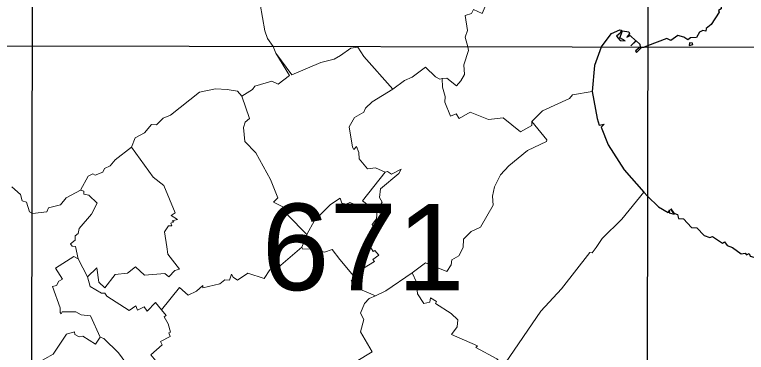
# Model space of a CAD drawing. Extents: x 483840 to 488445, y 4386047 to 4389027.
# Drawn here: x 488113.7 to 488278.3, y 4388075.6 to 4388151.7 of the extents above; entities that cross this region are included whole.
import ezdxf
from ezdxf.enums import TextEntityAlignment as Align

# ---------------------------------------------------------------- set-up
doc = ezdxf.new("R2010")
doc.units = 0
doc.header["$LTSCALE"] = 4
doc.linetypes.add('DOTTED', pattern=[1.5, 0.3, -1.2])
for name, color, linetype, lineweight in [('1', 7, 'Continuous', 13), ('2', 7, 'DOTTED', 13), ('3', 7, 'Continuous', 25)]:
    doc.layers.add(name, color=color, linetype=linetype, lineweight=lineweight)

msp = doc.modelspace()

# ---------------------------------------------------------------- linework, layer by layer
at = {"layer": '1', "lineweight": 25}
for p, q in [((488116.81, 4387693.08), (488117.86, 4388235.03)), ((488255.37, 4387692.81), (488256.42, 4388234.76)), ((487979.13, 4388144.96), (488394.81, 4388144.16))]:
    msp.add_line(p, q, dxfattribs=at)
at = {"layer": '3'}
msp.add_line((488256.11, 4388144.69), (488255.33, 4388144.38), dxfattribs=at)
at = {"layer": '3', "lineweight": 13}
msp.add_line((488171.85, 4388144.53), (488172.45, 4388143.01), dxfattribs=at)
for points in [[(488164.04, 4388180.35), (488162.48, 4388179.07), (488162.63, 4388175.3), (488163.18, 4388174.87), (488163.68, 4388173.06), (488163.73, 4388169.67), (488165.91, 4388166.46), (488167.69, 4388165.71), (488167.55, 4388163.6), (488168.76, 4388162.25), (488168.71, 4388160.94), (488169.4, 4388159.34), (488169.66, 4388157.36), (488169.51, 4388155.19), (488168.92, 4388154.04), (488169.96, 4388148.07), (488170.6, 4388146.32), (488171.85, 4388144.53)], [(488231.17, 4388164.34), (488228.87, 4388163.4), (488224.37, 4388157.78), (488222.57, 4388156.35), (488221.87, 4388155.14), (488220.08, 4388154.77), (488218.9, 4388151.95), (488216.97, 4388152.84), (488216.47, 4388152), (488215.05, 4388151.49), (488215.57, 4388148.17), (488215.09, 4388146.67), (488215.64, 4388144.44)], [(488172.45, 4388143.01), (488175.54, 4388138.02), (488173, 4388136.09), (488171.54, 4388136.73), (488167.69, 4388135.58), (488167.17, 4388134.85), (488164.81, 4388133.38)], [(488172.45, 4388143.01), (488176.05, 4388138.15), (488182.61, 4388140.92), (488185.61, 4388141.66), (488186.99, 4388142.51)], [(488198.76, 4388134.96), (488192.28, 4388142.29), (488190.88, 4388144.37), (488189.35, 4388144.13), (488186.99, 4388142.51)], [(488215.64, 4388144.44), (488215.83, 4388143.61), (488214.77, 4388140.44), (488214.88, 4388138.22), (488214.08, 4388136.84), (488213.11, 4388135.65), (488210.93, 4388137.41), (488209.88, 4388137.32)], [(488209.88, 4388137.32), (488209.37, 4388137.17), (488208.41, 4388137.72), (488206.1, 4388139.92), (488203.15, 4388137.65), (488201.38, 4388136.87), (488198.76, 4388134.96)], [(488230.06, 4388127.66), (488230.09, 4388126.71), (488227.5, 4388125.33), (488223.62, 4388128.44), (488220.32, 4388128.11), (488216.21, 4388129.72), (488213.69, 4388128.29), (488213.04, 4388129.4), (488211.76, 4388128.83), (488210.46, 4388132.03), (488210.59, 4388133.29), (488209.93, 4388135.37), (488209.88, 4388137.32)], [(488164.81, 4388133.38), (488163.84, 4388134.44), (488161.53, 4388134.86), (488158.89, 4388134.97), (488155.24, 4388134.28), (488148.75, 4388129.05), (488147.12, 4388128.42), (488145.58, 4388126.92), (488144.49, 4388126.94), (488142.92, 4388125.08), (488140.82, 4388123.97), (488139.98, 4388121.9)], [(488198.76, 4388134.96), (488194.14, 4388132.11), (488192.61, 4388130.65), (488192.26, 4388129.72), (488190.13, 4388128.52), (488188.92, 4388126.43), (488189.73, 4388121.87), (488189.98, 4388121.32), (488190.57, 4388122.02), (488191.14, 4388120.63), (488191.2, 4388119.2), (488193.09, 4388116.98), (488194.85, 4388117.24), (488197.06, 4388116.24)], [(488164.81, 4388133.38), (488166.56, 4388128.34), (488165.55, 4388127.46), (488165.16, 4388126.29), (488165.46, 4388123.12), (488167.93, 4388120.56), (488171.27, 4388114.58), (488172.92, 4388110.44), (488171.92, 4388109.47), (488174.96, 4388107.94), (488174.44, 4388107.44), (488175.08, 4388106.62), (488179.43, 4388102.16), (488178.31, 4388099.33)], [(488243.61, 4388134.37), (488239.22, 4388133.68), (488238.5, 4388132.84), (488232.47, 4388130.07), (488230.06, 4388127.66)], [(488230.06, 4388127.66), (488233.44, 4388123.49), (488233.35, 4388123.17), (488229.07, 4388121.1), (488224.86, 4388117.69), (488223.01, 4388115.65), (488221.67, 4388112.93), (488221.19, 4388110.79), (488221.36, 4388108.82), (488218.5, 4388103.82), (488216.42, 4388102.87), (488214.66, 4388101.11), (488214.63, 4388099.27)], [(488139.98, 4388121.9), (488136.28, 4388118.99), (488135.16, 4388117.65), (488133.91, 4388117.02), (488133.54, 4388116.23), (488131.77, 4388115.55), (488131.29, 4388115.85), (488130.22, 4388115.31), (488128.53, 4388112.21)], [(488139.98, 4388121.9), (488144.85, 4388115.08), (488147.28, 4388113.21), (488149.79, 4388107.06), (488148.9, 4388106.47), (488150.35, 4388105.59), (488149.16, 4388105.24), (488149.48, 4388105.05), (488148.8, 4388104.72), (488149.03, 4388104.17), (488148.27, 4388104.17), (488147.43, 4388102.77), (488147.91, 4388099.43)], [(488197.06, 4388116.24), (488197.59, 4388116.35), (488198.48, 4388115.78), (488200.63, 4388116.94), (488200.11, 4388115.91), (488196, 4388112.51), (488195.75, 4388110.51), (488196.38, 4388109.47), (488195.23, 4388107.67), (488195.14, 4388105.7), (488194.1, 4388104.44), (488195.1, 4388102.37), (488194.1, 4388102.14), (488193.05, 4388100.47), (488193.76, 4388099.3)], [(488197.06, 4388116.24), (488191.98, 4388109.79), (488193.5, 4388108.59), (488192.45, 4388107.18), (488190.06, 4388109.02), (488189.09, 4388109.37), (488188.29, 4388109), (488187.3, 4388109.25), (488186.92, 4388110.34)], [(488113.04, 4388112.95), (488114.99, 4388111.18), (488115.38, 4388109.76), (488116.38, 4388109.5), (488117.02, 4388107.33), (488117.72, 4388106.93)], [(488128.53, 4388112.21), (488125.27, 4388110.48), (488123.97, 4388108.88), (488121.28, 4388108.21), (488120.89, 4388107.29), (488117.72, 4388106.93)], [(488128.53, 4388112.21), (488129.26, 4388111.92), (488129.23, 4388111.27), (488130.39, 4388111.03), (488132.21, 4388109.22), (488131, 4388106.79), (488128.16, 4388103.55), (488127.94, 4388102.45), (488127.26, 4388101.88), (488127.27, 4388100.95), (488126.22, 4388100.07), (488126.62, 4388099.53), (488127.37, 4388099.5)], [(488255.24, 4388111.72), (488250.29, 4388105.67), (488245.9, 4388101.32), (488244.5, 4388099.24)], [(488186.92, 4388110.34), (488184.79, 4388108.92), (488181.17, 4388105.35), (488179.43, 4388102.16)], [(488127.37, 4388099.5), (488127.95, 4388096.72), (488130.05, 4388092.66)], [(488130.05, 4388092.66), (488132.15, 4388094.66), (488132.64, 4388091.49), (488133.96, 4388090.2), (488136.33, 4388093.21), (488139.04, 4388093.45), (488140.88, 4388094.88), (488142.92, 4388093.06), (488147.51, 4388093.42), (488148.38, 4388092.69), (488149.73, 4388094.06), (488150.76, 4388094.38), (488148.18, 4388097.78), (488147.91, 4388099.43)], [(488178.31, 4388099.33), (488173.03, 4388094.81), (488171.12, 4388094.25), (488169.86, 4388092.26), (488166.14, 4388093.48), (488163.83, 4388091.94), (488162.88, 4388092.57), (488162.51, 4388093.29), (488162.05, 4388091.91), (488161.01, 4388092.01), (488159.82, 4388091.05), (488156.02, 4388090.15), (488156, 4388090.72), (488154.61, 4388089.39), (488152.74, 4388088.53), (488150.77, 4388090.26), (488146.74, 4388085.23)], [(488178.31, 4388099.33), (488178.52, 4388098.88), (488180.65, 4388098.94), (488183.37, 4388098.22), (488185.12, 4388098.79), (488186.88, 4388096.54)], [(488193.76, 4388099.3), (488194.38, 4388098.36), (488194.71, 4388098.58), (488195.66, 4388097.54), (488194.28, 4388096.55), (488194.62, 4388096.12), (488191.98, 4388094.47), (488190.3, 4388092.44), (488186.88, 4388096.54)], [(488214.63, 4388099.27), (488213.66, 4388097.41), (488212.07, 4388096.52), (488211.91, 4388095.35), (488210.93, 4388093.88), (488206.12, 4388095.79), (488203.15, 4388093.53)], [(488224.16, 4388073.31), (488232.08, 4388084.89), (488236.77, 4388089.94), (488243.11, 4388098.16), (488243.61, 4388098.08), (488244.5, 4388099.24)], [(488127.95, 4388096.72), (488126.98, 4388097.2), (488122.89, 4388094.59), (488124.46, 4388092.1), (488123.62, 4388091.66), (488123.06, 4388090.72), (488122.23, 4388090.51), (488123.9, 4388085.66), (488123.89, 4388084.6), (488124.16, 4388084.35), (488124.4, 4388084.76), (488127.48, 4388084.78), (488128.67, 4388084.07), (488130.78, 4388083.86), (488132.89, 4388079.04)], [(488203.15, 4388093.53), (488197.22, 4388089.5), (488194.89, 4388088.35)], [(488203.15, 4388093.53), (488204.09, 4388091.47), (488204.34, 4388088.81), (488205.76, 4388086.61), (488207.08, 4388086.98), (488207.24, 4388087.92), (488208.61, 4388087.09), (488208.37, 4388086.66), (488211.89, 4388084.4), (488213.38, 4388082.97), (488213.26, 4388081.36), (488211.98, 4388079.63), (488217.83, 4388077.1), (488217.47, 4388076.74), (488222.21, 4388074.18), (488223.72, 4388072.75), (488224.16, 4388073.31)], [(488146.74, 4388085.23), (488145.38, 4388086.84), (488143.52, 4388084.93), (488142.83, 4388085.93), (488141.3, 4388085.11), (488140.95, 4388086.1), (488139.44, 4388085.05), (488134.43, 4388088.3), (488133.97, 4388088.99), (488133.21, 4388088.96), (488130.66, 4388090.46), (488130.05, 4388092.66)], [(488190.3, 4388092.44), (488189.41, 4388091.72), (488190.09, 4388091.41), (488189.76, 4388090.56), (488194.89, 4388088.35)], [(488194.89, 4388088.35), (488193.48, 4388087.75), (488192.38, 4388086.67), (488191.48, 4388084.47), (488192.27, 4388083.04), (488191.54, 4388080.29), (488194.16, 4388075.76), (488190.51, 4388073.6), (488191.05, 4388071.48), (488189.68, 4388069.49), (488189.21, 4388067.7), (488188.63, 4388067.51), (488188.94, 4388067.24), (488187.57, 4388066.06), (488186.81, 4388064.83)], [(488146.74, 4388085.23), (488147.74, 4388083.91), (488147.34, 4388083.64), (488148.25, 4388082.05), (488148.74, 4388080.16), (488148.38, 4388080.07), (488148.66, 4388079.24), (488146.48, 4388078.1), (488146.87, 4388077.34), (488144.33, 4388075.1), (488146.55, 4388072.39), (488145.73, 4388071.9), (488147.27, 4388069.55), (488145.91, 4388068.43)], [(488132.89, 4388079.04), (488131.89, 4388077.49), (488129.04, 4388079.3), (488128.21, 4388079.16), (488127.25, 4388079.67), (488127.13, 4388080.23), (488125.34, 4388079.76), (488122.37, 4388075.21), (488118.57, 4388073.12), (488117.67, 4388071.41), (488117.98, 4388069.64), (488117.58, 4388069.33)], [(488145.91, 4388068.43), (488144.36, 4388070.76), (488141.65, 4388069.34), (488137.02, 4388075.54), (488133.76, 4388078.8), (488132.89, 4388079.04)]]:
    msp.add_lwpolyline(points, dxfattribs=at)
at = {"layer": '3'}
for points in [[(488275.68, 4388159.47), (488276.93, 4388159.92), (488276.37, 4388157.76), (488273.32, 4388153.82), (488272.67, 4388153.74), (488272.69, 4388153), (488272.09, 4388152.64), (488272.25, 4388152.24), (488270.4, 4388149.51), (488269.26, 4388148.58), (488269.22, 4388147.96), (488268.51, 4388148.12), (488267.78, 4388147.77), (488267.09, 4388146.53), (488265.76, 4388146.5), (488265.13, 4388146.05), (488264.27, 4388146.67)], [(488245.64, 4388144.4), (488247.96, 4388147.46), (488249.87, 4388148.26), (488250.23, 4388148.23), (488249.95, 4388147.52), (488249.14, 4388146.84), (488249.93, 4388145.88), (488251.07, 4388145.81), (488249.89, 4388146.52), (488250.43, 4388148.07), (488251.91, 4388147.84), (488252.06, 4388147.41), (488251.46, 4388146.67), (488252.2, 4388147.04), (488253.45, 4388145.82), (488252.32, 4388144.67), (488253.52, 4388145.79), (488254.33, 4388145.04), (488254.44, 4388144.39)], [(488264.27, 4388146.67), (488262.9, 4388147.01), (488261.31, 4388145.9), (488260.41, 4388146.36), (488256.11, 4388144.69)], [(488245.64, 4388144.4), (488244.13, 4388140.27), (488243.61, 4388134.37)], [(488254.44, 4388144.39), (488253.4, 4388143.56), (488253.59, 4388143.18), (488254.74, 4388144.32), (488255.33, 4388144.38)], [(488243.61, 4388134.37), (488244.73, 4388128.31), (488245.21, 4388126.8), (488246.33, 4388127.01), (488245.66, 4388126.35), (488247.21, 4388122.39), (488250.82, 4388116.79), (488255.24, 4388111.72), (488256.09, 4388110.83)], [(488256.09, 4388110.83), (488258.59, 4388108.41), (488260.71, 4388107.16), (488261.03, 4388107.72), (488260.99, 4388107.09), (488262.07, 4388106.8), (488261.37, 4388107.98), (488262.03, 4388106.98), (488262.83, 4388106.69), (488263.1, 4388105.82), (488264.16, 4388105.75), (488265.97, 4388103.79)], [(488265.97, 4388103.79), (488267.22, 4388103.66), (488268.84, 4388101.98), (488270.12, 4388101.51), (488270.7, 4388101.73), (488272.99, 4388100.23), (488273.44, 4388100.57), (488274, 4388099.73), (488275.21, 4388099.24)], [(488275.21, 4388099.24), (488277.18, 4388097.87), (488278.09, 4388098), (488278.38, 4388097.62), (488278.93, 4388097.9), (488279.2, 4388097.28), (488280.55, 4388096.91), (488280.95, 4388096.08), (488281.69, 4388095.83), (488283.39, 4388094.07), (488286.31, 4388093.05), (488286.88, 4388092.92), (488286.57, 4388093.23), (488286.84, 4388093.25), (488287.38, 4388092.63)]]:
    msp.add_lwpolyline(points, dxfattribs=at)
msp.add_lwpolyline([(488265.56, 4388145.35), (488265.43, 4388144.74), (488266.31, 4388144.97), (488266.24, 4388145.32)], close=True, dxfattribs=at)

# ---------------------------------------------------------------- texts
at = {"layer": '2', "width": 1.05}
msp.add_text('671', height=19.5, rotation=359.889, dxfattribs=at).set_placement((488192.1, 4388089.62), align=Align.CENTER)

doc.saveas('drawing.dxf')
